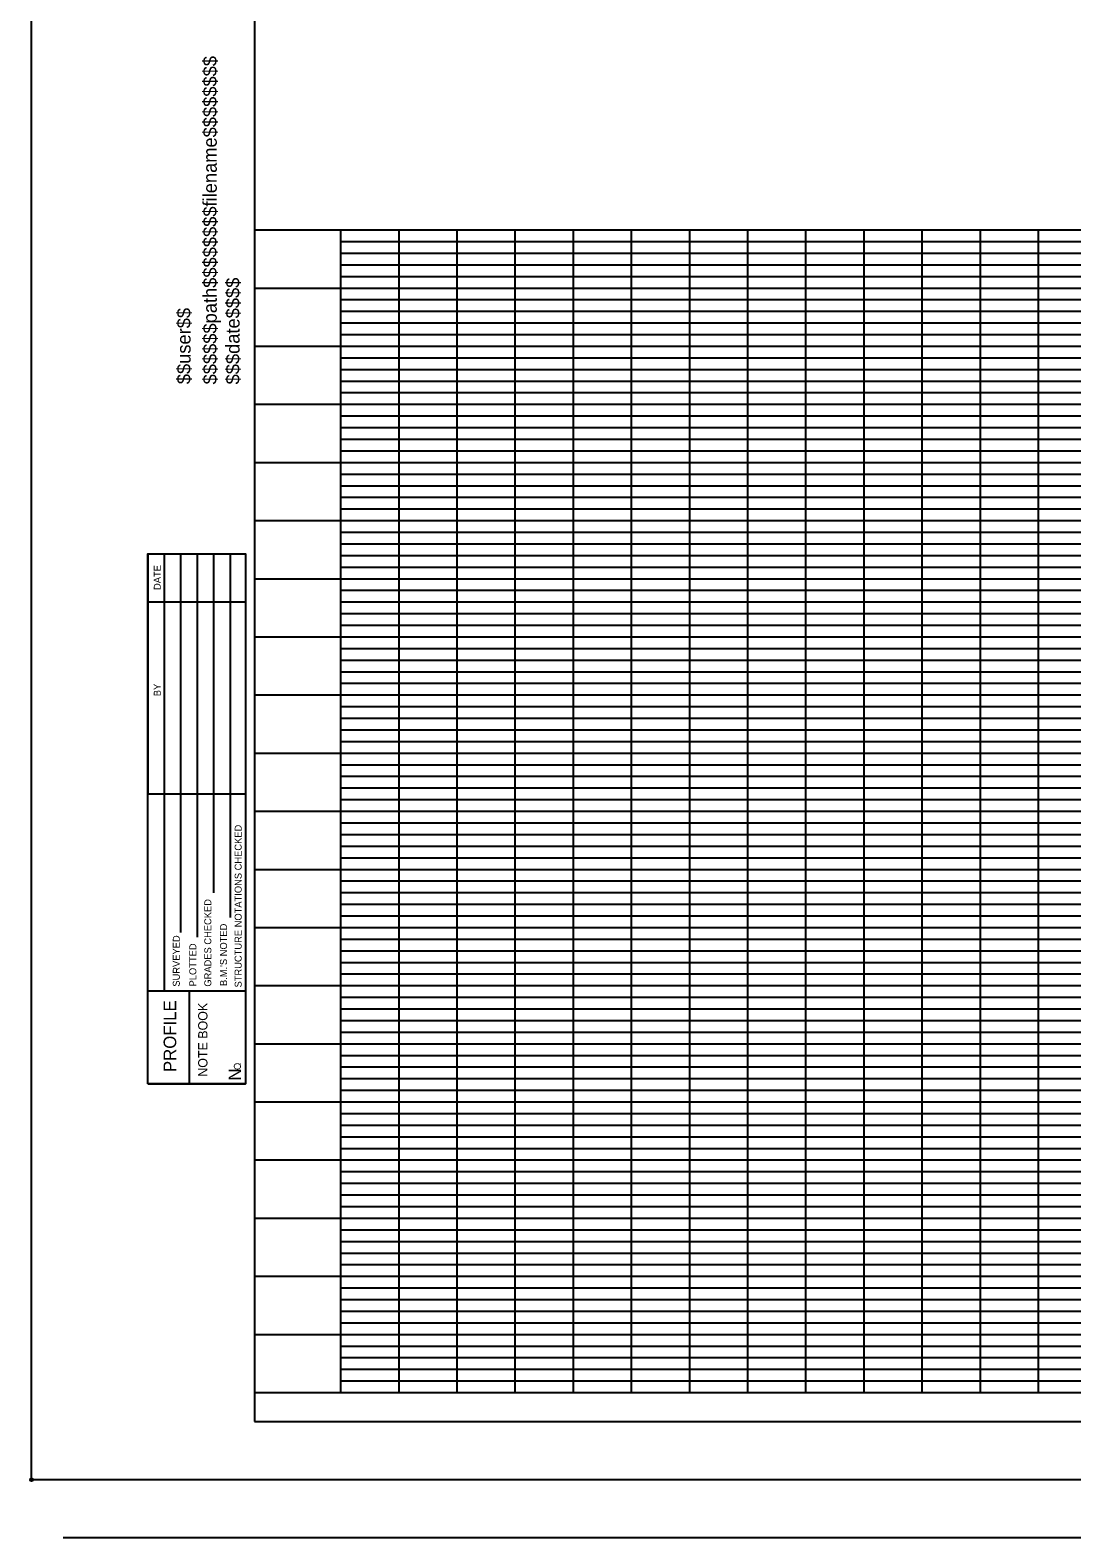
# Model space of a CAD drawing. Extents: x -184 to 1613, y -563 to 2888.
# Drawn here: x -184 to 264, y -563 to 86 of the extents above; entities that cross this region are included whole.
import ezdxf

# ---------------------------------------------------------------- set-up
doc = ezdxf.new("R2010")
doc.units = 0
for name, color, linetype in [('Default', 7, 'Continuous'), ('RD_SHT_Bndy', 7, 'Continuous'), ('RD_SHT_ID', 7, 'Continuous'), ('RD_SHT_IplotShp', 7, 'Continuous'), ('RD_SHT_MjGrid', 7, 'Continuous'), ('RD_SHT_MnGrid', 7, 'Continuous'), ('RD_SHT_Snap', 7, 'Continuous'), ('RD_SHT_SubGrid', 7, 'Continuous'), ('RD_SHT_TX', 7, 'Continuous')]:
    doc.layers.add(name, color=color, linetype=linetype)

msp = doc.modelspace()

# ---------------------------------------------------------------- linework, layer by layer
at = {"layer": 'Default'}
msp.add_circle((-182.9, -537.5), 0.607, dxfattribs=at)
at = {"layer": 'RD_SHT_Bndy'}
for p, q in [((-87, 537.5), (-87, -512.5)), ((-87, 0), (1588, 0)), ((-50, 0), (-50, -500)), ((-132.95, -139.3), (-132.95, -242.5)), ((-125.85, -139.3), (-125.85, -327.25)), ((-118.8, -139.3), (-118.8, -302.2)), ((-111.7, -139.3), (-111.7, -304.2)), ((-104.65, -139.3), (-104.65, -285.1)), ((-97.55, -139.3), (-97.55, -295.65)), ((-132.95, -159.95), (-90.95, -159.95)), ((-132.95, -242.5), (-90.95, -242.5)), ((-132.95, -327.3), (-90.95, -327.3)), ((-132.95, -367.3), (-132.95, -327.3)), ((-114.95, -367.3), (-114.95, -327.3)), ((-132.95, -367.3), (-90.95, -367.3)), ((-87, -500), (1588, -500)), ((-87, -512.5), (1588, -512.5)), ((1590.65, -537.5), (-169.35, -537.5)), ((1590.65, -562.5), (-169.35, -562.5))]:
    msp.add_line(p, q, dxfattribs=at)
msp.add_lwpolyline([(-132.95, -367.3), (-132.95, -139.3), (-90.95, -139.3), (-90.95, -367.3)], close=True, dxfattribs=at)
at = {"layer": 'RD_SHT_IplotShp'}
msp.add_lwpolyline([(-182.9, 562.5), (1613, 562.5), (1613, -537.5), (-182.9, -537.5)], close=True, dxfattribs=at)
at = {"layer": 'RD_SHT_MjGrid'}
for p, q in [((0, 0), (0, -500)), ((50, 0), (50, -500)), ((100, 0), (100, -500)), ((150, 0), (150, -500)), ((200, 0), (200, -500)), ((250, 0), (250, -500)), ((-87, -50), (1588, -50)), ((-87, -100), (1588, -100)), ((-87, -150), (1588, -150)), ((-87, -200), (1588, -200)), ((-87, -250), (1588, -250)), ((-87, -300), (1588, -300)), ((-87, -350), (1588, -350)), ((-87, -400), (1588, -400)), ((-87, -450), (1588, -450))]:
    msp.add_line(p, q, dxfattribs=at)
at = {"layer": 'RD_SHT_MnGrid'}
for p, q in [((-25, 0), (-25, -500)), ((25, 0), (25, -500)), ((75, 0), (75, -500)), ((125, 0), (125, -500)), ((175, 0), (175, -500)), ((225, 0), (225, -500)), ((-87, -25), (1588, -25)), ((-87, -75), (1588, -75)), ((-87, -125), (1588, -125)), ((-87, -175), (1588, -175)), ((-87, -225), (1588, -225)), ((-87, -275), (1588, -275)), ((-87, -325), (1588, -325)), ((-87, -375), (1588, -375)), ((-87, -425), (1588, -425)), ((-87, -475), (1588, -475))]:
    msp.add_line(p, q, dxfattribs=at)
at = {"layer": 'RD_SHT_Snap'}
msp.add_line((-182.9, -537.5), (-182.9, 562.5), dxfattribs=at)
at = {"layer": 'RD_SHT_SubGrid'}
for p, q in [((-49.95, -5), (1549.8, -5)), ((-49.95, -10), (1549.25, -10)), ((-49.95, -15), (1549.8, -15)), ((-49.9, -20), (1549.8, -20)), ((-49.95, -30), (1549.8, -30)), ((-49.95, -35), (1548.75, -35)), ((-49.95, -40), (1549.25, -40)), ((-49.95, -45), (1549.8, -45)), ((-49.95, -55), (1549.8, -55)), ((-49.95, -60), (1549.8, -60)), ((-49.95, -65), (1549.25, -65)), ((-49.95, -70), (1549.8, -70)), ((-49.95, -80), (1548.75, -80)), ((-49.95, -85), (1548.75, -85)), ((-49.95, -90), (1549.25, -90)), ((-49.95, -95), (1549.25, -95)), ((-49.95, -105), (1548.75, -105)), ((-49.95, -110), (1549.25, -110)), ((-49.95, -115), (1548.75, -115)), ((-49.9, -120), (1549.8, -120)), ((-49.95, -130), (1549.25, -130)), ((-49.95, -135), (1549.25, -135)), ((-49.95, -140), (1549.25, -140)), ((-49.95, -145), (1549.25, -145)), ((-49.85, -155), (1548.75, -155)), ((-49.85, -160), (1548.75, -160)), ((-49.9, -165), (1549.25, -165)), ((-49.9, -170), (1549.25, -170)), ((-49.95, -180), (1549.25, -180)), ((-49.95, -185), (1549.25, -185)), ((-49.95, -190), (1548.75, -190)), ((-49.95, -195), (1549.25, -195)), ((-49.95, -195), (1549.25, -195)), ((-49.95, -205), (1549.8, -205)), ((-49.95, -210), (1549.8, -210)), ((-49.95, -215), (1549.8, -215)), ((-49.95, -220), (1549.8, -220)), ((-49.95, -230), (1549.8, -230)), ((-49.95, -235), (1549.8, -235)), ((-49.95, -240), (1549.8, -240)), ((-49.95, -245), (1549.8, -245)), ((-49.95, -255), (1549.85, -255)), ((-49.95, -260), (1549.85, -260)), ((-49.95, -265), (1549.85, -265)), ((-49.95, -270), (1549.85, -270)), ((-49.95, -280), (1549.85, -280)), ((-49.95, -285), (1549.85, -285)), ((-49.95, -290), (1549.85, -290)), ((-49.95, -295), (1549.85, -295)), ((-49.95, -305), (1549.85, -305)), ((-49.95, -310), (1549.85, -310)), ((-49.95, -315), (1549.85, -315)), ((-49.95, -320), (1549.85, -320)), ((-49.95, -330), (1549.85, -330)), ((-49.9, -330), (1549.85, -330)), ((-49.95, -335), (1549.85, -335)), ((-49.9, -340), (1549.6, -340)), ((-49.9, -345), (1549.6, -345)), ((-49.9, -355), (1549.8, -355)), ((-49.95, -360), (1549.95, -360)), ((-49.95, -365), (1549.95, -365)), ((-49.9, -370), (1549.95, -370)), ((-49.95, -380), (1549.95, -380)), ((-49.95, -385), (1549.95, -385)), ((-49.95, -390), (1549.95, -390)), ((-49.9, -395), (1549.95, -395)), ((-49.95, -405), (1549.95, -405)), ((-49.95, -410), (1549.95, -410)), ((-49.95, -415), (1549.95, -415)), ((-49.95, -420), (1549.85, -420)), ((-49.9, -430), (1549.6, -430)), ((-49.95, -435), (1549.85, -435)), ((-49.95, -440), (1549.85, -440)), ((-49.95, -445), (1549.85, -445)), ((-49.95, -460), (1549.85, -460)), ((-49.85, -455), (1549.85, -455)), ((-49.95, -465), (1549.85, -465)), ((-49.95, -470), (1549.85, -470)), ((-49.85, -480), (1549.85, -480)), ((-49.85, -485), (1549.85, -485)), ((-49.85, -490), (1549.85, -490)), ((-49.85, -495), (1549.85, -495))]:
    msp.add_line(p, q, dxfattribs=at)

# ---------------------------------------------------------------- texts
at = {"layer": 'RD_SHT_ID'}
for s, p in [('$$$$$$path$$$$$$$$filename$$$$$$$$', (-103.25, -66.45)), ('$$$date$$$$', (-93.45, -66.45)), ('$$user$$', (-114.5, -66.35))]:
    msp.add_text(s, height=5.88, rotation=90, dxfattribs=at).set_placement(p)
at = {"layer": 'RD_SHT_TX'}
for s, height, p in [('DATE', 3, (-127.35, -154.85)), ('BY', 3, (-127.35, -200.55)), ('STRUCTURE NOTATIONS CHECKED', 3, (-92.55, -325.8)), ('GRADES CHECKED', 3, (-105.6, -325.45)), ('SURVEYED', 3, (-119.15, -325.45)), ("B.M.'S NOTED", 3, (-98.85, -325.2)), ('PLOTTED', 3, (-112.05, -325.35)), ('PROFILE', 5.4, (-120.7, -362.2)), ('NOTE BOOK', 4, (-107.25, -364.2)), ('N', 5.4, (-92.8, -365.85)), ('O', 3, (-92.9, -361.3))]:
    msp.add_text(s, height=height, rotation=90, dxfattribs=at).set_placement(p)
msp.add_text('.', height=3, dxfattribs=at).set_placement((-93.55, -358.9))

doc.saveas('drawing.dxf')
